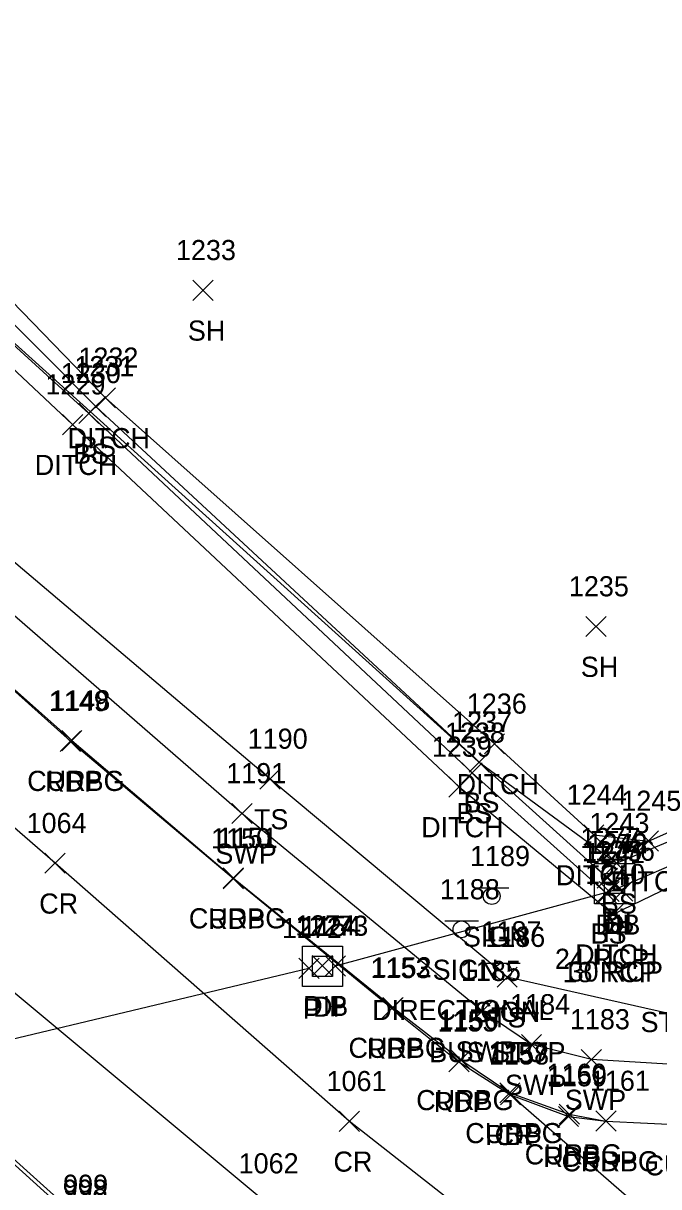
# Model space of a CAD drawing. Extents: x 1688195 to 1692013, y 424605 to 441234.
# Drawn here: x 1691891.2 to 1691954.3, y 439243.2 to 439358.8 of the extents above; entities that cross this region are included whole.
import ezdxf

# ---------------------------------------------------------------- set-up
doc = ezdxf.new("R2010")
doc.units = 0
for name, color, linetype in [('D_A', 7, 'Continuous'), ('D_C', 7, 'Continuous'), ('D_I', 7, 'Continuous'), ('D_TIC', 7, 'Continuous'), ('DCP', 7, 'Continuous'), ('DD', 7, 'Continuous'), ('DS', 7, 'Continuous'), ('L_A', 7, 'Continuous'), ('L_I', 7, 'Continuous'), ('L_TIC', 7, 'Continuous'), ('LELB', 7, 'Continuous'), ('P_A', 7, 'Continuous'), ('P_I', 7, 'Continuous'), ('P_TIC', 7, 'Continuous'), ('PET', 7, 'Continuous'), ('PRC', 7, 'Continuous'), ('R_A', 7, 'Continuous'), ('R_I', 7, 'Continuous'), ('R_TIC', 7, 'Continuous'), ('RC', 7, 'Continuous'), ('RSW', 7, 'Continuous'), ('S_A', 7, 'Continuous'), ('S_C', 7, 'Continuous'), ('S_I', 7, 'Continuous'), ('SSGN', 7, 'Continuous')]:
    doc.layers.add(name, color=color, linetype=linetype)

msp = doc.modelspace()

# ---------------------------------------------------------------- linework, layer by layer
at = {"layer": 'D_TIC'}
for points in [[(1691898.36, 439320.57), (1691900.36, 439322.57)], [(1691900.36, 439320.57), (1691898.36, 439322.57)], [(1691895.1, 439317.91), (1691897.1, 439319.91)], [(1691897.1, 439317.91), (1691895.1, 439319.91)], [(1691936.96, 439286.21), (1691938.96, 439288.21)], [(1691938.96, 439286.21), (1691936.96, 439288.21)], [(1691933.44, 439281.93), (1691935.44, 439283.93)], [(1691935.44, 439281.93), (1691933.44, 439283.93)], [(1691946.81, 439277.16), (1691948.81, 439279.16)], [(1691948.81, 439277.16), (1691946.81, 439279.16)], [(1691952.23, 439276.56), (1691954.23, 439278.56)], [(1691954.23, 439276.56), (1691952.23, 439278.56)], [(1691948.16, 439272.86), (1691950.16, 439274.86)], [(1691950.16, 439272.86), (1691948.16, 439274.86)], [(1691948.34, 439271.54), (1691950.34, 439273.54)], [(1691950.34, 439271.54), (1691948.34, 439273.54)], [(1691948.87, 439272.26), (1691950.87, 439274.26)], [(1691950.87, 439272.26), (1691948.87, 439274.26)], [(1691949.67, 439271.6), (1691951.67, 439273.6)], [(1691951.67, 439271.6), (1691949.67, 439273.6)], [(1691948.73, 439269.29), (1691950.73, 439271.29)], [(1691950.73, 439269.29), (1691948.73, 439271.29)], [(1691918.55, 439263.92), (1691920.55, 439265.92)], [(1691920.55, 439263.92), (1691918.55, 439265.92)], [(1691919.88, 439264.18), (1691921.88, 439266.18)], [(1691921.88, 439264.18), (1691919.88, 439266.18)], [(1691921.17, 439264.15), (1691923.17, 439266.15)], [(1691923.17, 439264.15), (1691921.17, 439266.15)]]:
    msp.add_lwpolyline(points, dxfattribs=at)
at = {"layer": 'DCP'}
for points in [[(1691949.16, 439273.86), (1691789.03, 439418.46)], [(1691922.17, 439265.15), (1691949.34, 439272.54)], [(1691871.63, 439253.48), (1691919.55, 439264.92)]]:
    msp.add_lwpolyline(points, dxfattribs=at)
at = {"layer": 'DD'}
for points in [[(1691845, 439386.65), (1691846.96, 439371.91), (1691853.76, 439362.04), (1691874.03, 439339.66), (1691896.1, 439318.91), (1691934.44, 439282.93), (1691949.73, 439270.29), (1691969.73, 439279.96), (1691978.58, 439270.8)], [(1691849.48, 439383.4), (1691851.48, 439372.69), (1691857.96, 439364.8), (1691877.63, 439343.99), (1691899.36, 439321.57), (1691937.96, 439287.21), (1691947.81, 439278.16), (1691953.23, 439277.56), (1691972.91, 439286.3), (1691980.77, 439274.16), (1691984.62, 439267.72)]]:
    msp.add_lwpolyline(points, dxfattribs=at)
at = {"layer": 'DS'}
for p, q in [((1691947.87, 439275.33), (1691951.87, 439275.33)), ((1691947.87, 439271.33), (1691947.87, 439275.33)), ((1691951.87, 439275.33), (1691951.87, 439271.33)), ((1691948.87, 439272.33), (1691948.87, 439274.33)), ((1691948.87, 439274.33), (1691950.87, 439274.33)), ((1691950.87, 439274.33), (1691950.87, 439272.33)), ((1691950.87, 439272.33), (1691948.87, 439272.33)), ((1691949.87, 439273.33), (1691949.87, 439273.33)), ((1691949.87, 439273.33), (1691949.87, 439273.33)), ((1691951.87, 439271.33), (1691947.87, 439271.33)), ((1691918.89, 439267.11), (1691922.89, 439267.11)), ((1691918.89, 439263.11), (1691918.89, 439267.11)), ((1691922.89, 439267.11), (1691922.89, 439263.11)), ((1691919.89, 439264.11), (1691919.89, 439266.11)), ((1691919.89, 439266.11), (1691921.89, 439266.11)), ((1691921.89, 439266.11), (1691921.89, 439264.11)), ((1691920.9, 439265.11), (1691920.9, 439265.11)), ((1691920.9, 439265.11), (1691920.9, 439265.11)), ((1691922.89, 439263.11), (1691918.89, 439263.11)), ((1691921.89, 439264.11), (1691919.89, 439264.11))]:
    msp.add_line(p, q, dxfattribs=at)
at = {"layer": 'L_TIC'}
for points in [[(1691908.04, 439331.25), (1691910.04, 439333.25)], [(1691910.04, 439331.25), (1691908.04, 439333.25)], [(1691896.71, 439319.03), (1691898.71, 439321.03)], [(1691898.71, 439319.03), (1691896.71, 439321.03)], [(1691897.4, 439319.72), (1691899.4, 439321.72)], [(1691899.4, 439319.72), (1691897.4, 439321.72)], [(1691947.03, 439297.86), (1691949.03, 439299.86)], [(1691949.03, 439297.86), (1691947.03, 439299.86)], [(1691935.44, 439284.39), (1691937.44, 439286.39)], [(1691937.44, 439284.39), (1691935.44, 439286.39)], [(1691934.73, 439283.32), (1691936.73, 439285.32)], [(1691936.73, 439283.32), (1691934.73, 439285.32)], [(1691914.68, 439282.72), (1691916.68, 439284.72)], [(1691916.68, 439282.72), (1691914.68, 439284.72)], [(1691949.07, 439274.35), (1691951.07, 439276.35)], [(1691951.07, 439274.35), (1691949.07, 439276.35)], [(1691948.05, 439271.37), (1691950.05, 439273.37)], [(1691950.05, 439271.37), (1691948.05, 439273.37)], [(1691938.22, 439263.04), (1691940.22, 439265.04)], [(1691940.22, 439263.04), (1691938.22, 439265.04)]]:
    msp.add_lwpolyline(points, dxfattribs=at)
at = {"layer": 'LELB'}
for points in [[(1691975.61, 439270.6), (1691971.42, 439266.02), (1691960.53, 439259.24), (1691939.22, 439264.04), (1691915.68, 439283.72), (1691886.97, 439308.05), (1691860.47, 439334.67), (1691845.99, 439348.3), (1691840.06, 439356.7), (1691834.35, 439370.12), (1691833.78, 439391.58)], [(1691846.65, 439384.74), (1691848.68, 439371.88), (1691855.16, 439363.03), (1691875.02, 439340.72), (1691897.71, 439320.03), (1691935.73, 439284.32), (1691949.05, 439272.37), (1691970.06, 439281.46), (1691980.12, 439271.73), (1691983.03, 439266.51)], [(1691847.58, 439384.47), (1691849.65, 439372.1), (1691856.36, 439363.87), (1691876.41, 439342.83), (1691898.4, 439320.72), (1691936.44, 439285.39), (1691950.07, 439275.35), (1691972.13, 439284.54), (1691980.12, 439271.73)]]:
    msp.add_lwpolyline(points, dxfattribs=at)
at = {"layer": 'P_TIC'}
for points in [[(1691894.87, 439286.46), (1691896.87, 439288.46)], [(1691896.87, 439286.46), (1691894.87, 439288.46)], [(1691893.35, 439274.35), (1691895.35, 439276.35)], [(1691895.35, 439274.35), (1691893.35, 439276.35)], [(1691911.05, 439272.82), (1691913.05, 439274.82)], [(1691913.05, 439272.82), (1691911.05, 439274.82)], [(1691926.79, 439259.94), (1691928.79, 439261.94)], [(1691928.79, 439259.94), (1691926.79, 439261.94)], [(1691933.43, 439254.64), (1691935.43, 439256.64)], [(1691935.43, 439254.64), (1691933.43, 439256.64)], [(1691938.54, 439251.36), (1691940.54, 439253.36)], [(1691940.54, 439251.36), (1691938.54, 439253.36)], [(1691938.54, 439251.36), (1691940.54, 439253.36)], [(1691940.54, 439251.36), (1691938.54, 439253.36)], [(1691922.55, 439248.72), (1691924.55, 439250.72)], [(1691924.55, 439248.72), (1691922.55, 439250.72)], [(1691944.3, 439249.2), (1691946.3, 439251.2)], [(1691946.3, 439249.2), (1691944.3, 439251.2)], [(1691948.02, 439248.75), (1691950.02, 439250.75)], [(1691950.02, 439248.75), (1691948.02, 439250.75)]]:
    msp.add_lwpolyline(points, dxfattribs=at)
at = {"layer": 'PET'}
for points in [[(1691800.95, 439315.05), (1691800.71, 439316.53), (1691801.54, 439317.59), (1691803.01, 439317.75), (1691817.06, 439309.7), (1691828.51, 439300.65), (1691844.68, 439285.42), (1691865.17, 439267.39), (1691884.85, 439250.83), (1691897.53, 439239.42), (1691910.3, 439227.43), (1691911.52, 439225.27), (1691910.89, 439223.79), (1691909.81, 439223.42), (1691908.76, 439223.6), (1691890.09, 439233.4), (1691870.38, 439245.17), (1691862.38, 439250.39), (1691860.03, 439251.8), (1691851, 439258.94), (1691829.1, 439279.04), (1691821.39, 439286.91), (1691810.78, 439300.43)], [(1691876.93, 439304.47), (1691895.87, 439287.46), (1691912.05, 439273.82), (1691927.79, 439260.94), (1691934.43, 439255.64), (1691939.54, 439252.36), (1691945.3, 439250.2), (1691949.02, 439249.75), (1691957.26, 439249.35), (1691965.7, 439251.38), (1691970.56, 439254.07), (1691975.68, 439258.27), (1691977.47, 439260.47), (1691979.88, 439263.5), (1691983.03, 439266.51), (1691984.62, 439267.72)]]:
    msp.add_lwpolyline(points, dxfattribs=at)
at = {"layer": 'PRC'}
for points in [[(1691980.66, 439193.96), (1691949.03, 439215.61), (1691915.39, 439241.55), (1691887.2, 439265.05), (1691850.38, 439298.07), (1691824.99, 439321.73), (1691796.94, 439350.89), (1691771.5, 439379.22), (1691742.05, 439414.41)], [(1691957.02, 439223.44), (1691923.55, 439249.72), (1691894.35, 439275.35), (1691862.96, 439302.59), (1691832.42, 439330.49), (1691805.17, 439357.5)], [(1691939.54, 439252.36), (1691968.23, 439227.36), (1692010.35, 439194.63)]]:
    msp.add_lwpolyline(points, dxfattribs=at)
at = {"layer": 'R_TIC'}
for points in [[(1691895.01, 439286.53), (1691897.01, 439288.53)], [(1691897.01, 439286.53), (1691895.01, 439288.53)], [(1691911.9, 439279.3), (1691913.9, 439281.3)], [(1691913.9, 439279.3), (1691911.9, 439281.3)], [(1691911.05, 439272.88), (1691913.05, 439274.88)], [(1691913.05, 439272.88), (1691911.05, 439274.88)], [(1691926.89, 439260.02), (1691928.89, 439262.02)], [(1691928.89, 439260.02), (1691926.89, 439262.02)], [(1691935.74, 439259.66), (1691937.74, 439261.66)], [(1691937.74, 439259.66), (1691935.74, 439261.66)], [(1691940.63, 439256.35), (1691942.63, 439258.35)], [(1691942.63, 439256.35), (1691940.63, 439258.35)], [(1691933.61, 439254.83), (1691935.61, 439256.83)], [(1691935.61, 439254.83), (1691933.61, 439256.83)], [(1691946.57, 439254.86), (1691948.57, 439256.86)], [(1691948.57, 439254.86), (1691946.57, 439256.86)], [(1691938.48, 439251.55), (1691940.48, 439253.55)], [(1691940.48, 439251.55), (1691938.48, 439253.55)], [(1691944.38, 439249.44), (1691946.38, 439251.44)], [(1691946.38, 439249.44), (1691944.38, 439251.44)], [(1691948.02, 439248.75), (1691950.02, 439250.75)], [(1691950.02, 439248.75), (1691948.02, 439250.75)]]:
    msp.add_lwpolyline(points, dxfattribs=at)
at = {"layer": 'RC'}
for points in [[(1691827.7, 439394.92), (1691826.17, 439390.37), (1691824.81, 439382.88), (1691824.34, 439378.12), (1691824.34, 439373.75), (1691825.06, 439368.5), (1691826.85, 439361.6), (1691828.4, 439357.54), (1691830.44, 439353.69), (1691834.78, 439346.96), (1691839.16, 439341.39), (1691852.5, 439327.72), (1691876.91, 439304.53), (1691896.01, 439287.53), (1691912.05, 439273.88), (1691927.89, 439261.02), (1691934.61, 439255.83), (1691939.48, 439252.55), (1691945.38, 439250.44), (1691949.02, 439249.75)], [(1691801.25, 439315.04), (1691801.11, 439316.33), (1691801.76, 439317.38), (1691802.82, 439317.35), (1691816.87, 439309.41), (1691828.25, 439300.3), (1691844.42, 439285.11), (1691865.02, 439267.12), (1691884.74, 439250.47), (1691897.46, 439238.93), (1691910.16, 439227.13), (1691911.27, 439225.37), (1691910.65, 439224.03), (1691909.84, 439223.78), (1691908.93, 439223.98), (1691890.41, 439233.73), (1691870.59, 439245.45), (1691863.21, 439250.36), (1691862.38, 439250.39)]]:
    msp.add_lwpolyline(points, dxfattribs=at)
at = {"layer": 'RSW'}
msp.add_lwpolyline([(1691977.46, 439268.16), (1691972.67, 439263.18), (1691966.62, 439257.98), (1691961.86, 439255.83), (1691956.78, 439255.3), (1691947.57, 439255.86), (1691941.63, 439257.35), (1691936.74, 439260.66), (1691912.9, 439280.3), (1691884.49, 439305), (1691857.04, 439330.93), (1691842.61, 439345.6), (1691837.43, 439352.31), (1691833.75, 439359.53), (1691830.58, 439369.1), (1691830.34, 439383.86), (1691832.59, 439392.6)], dxfattribs=at)
at = {"layer": 'SSGN'}
for p, q in [((1691936.04, 439272.92), (1691939.37, 439272.92)), ((1691937.68, 439272.09), (1691937.68, 439272.09)), ((1691933.03, 439269.62), (1691936.36, 439269.62)), ((1691934.68, 439268.79), (1691934.68, 439268.79)), ((1691937.17, 439265.44), (1691940.5, 439265.44)), ((1691938.82, 439264.61), (1691938.82, 439264.61))]:
    msp.add_line(p, q, dxfattribs=at)
for centre in [(1691937.68, 439272.09), (1691934.68, 439268.79), (1691938.82, 439264.61)]:
    msp.add_circle(centre, 0.833, dxfattribs=at)

# ---------------------------------------------------------------- texts
at = {"layer": 'D_A'}
for s, p in [('DITCH', (1691895.6, 439316.57)), ('DITCH', (1691892.34, 439313.91)), ('DITCH', (1691934.2, 439282.21)), ('DITCH', (1691930.68, 439277.93)), ('DITCH', (1691944.05, 439273.16)), ('DITCH', (1691949.47, 439272.56)), ('DIB', (1691947.97, 439268.26)), ('P', (1691948.54, 439268.86)), ('DI', (1691948.93, 439268.33)), ('P', (1691948.72, 439267.54)), ('P', (1691950.05, 439267.6)), ('DITCH', (1691945.96, 439265.29)), ('P', (1691918.93, 439259.92)), ('DIB', (1691918.98, 439260.18)), ('DI', (1691919.95, 439260.11)), ('P', (1691921.55, 439260.15))]:
    msp.add_text(s, height=2, dxfattribs=at).set_placement(p)
at = {"layer": 'D_C'}
for s, p in [('24 RCP', (1691943.95, 439264.86)), ('18 RCP', (1691944.7, 439263.54)), ('30 RCP', (1691945.31, 439263.6))]:
    msp.add_text(s, height=2, dxfattribs=at).set_placement(p)
at = {"layer": 'D_I'}
for s, p in [('1232', (1691896.67, 439324.57)), ('1229', (1691893.4, 439321.91)), ('1236', (1691935.21, 439290.21)), ('1239', (1691931.74, 439285.93)), ('1244', (1691945.12, 439281.16)), ('1245', (1691950.54, 439280.56)), ('1277', (1691946.47, 439276.86)), ('1242', (1691947.18, 439276.33)), ('1278', (1691947.18, 439276.26)), ('1275', (1691946.65, 439275.54)), ('1276', (1691947.92, 439275.6)), ('1240', (1691946.95, 439273.29)), ('1272', (1691916.86, 439267.92)), ('1274', (1691918.19, 439268.18)), ('1154', (1691918.77, 439268.11)), ('1273', (1691919.48, 439268.15))]:
    msp.add_text(s, height=2, dxfattribs=at).set_placement(p)
at = {"layer": 'L_A'}
for s, p in [('SH', (1691907.53, 439327.25)), ('BS', (1691896.84, 439315.72)), ('BS', (1691896.15, 439315.03)), ('SH', (1691946.52, 439293.86)), ('BS', (1691934.88, 439280.39)), ('TS', (1691914.09, 439278.72)), ('BS', (1691934.17, 439279.32)), ('BS', (1691948.51, 439270.35)), ('BS', (1691947.49, 439267.37)), ('TS', (1691937.63, 439259.04))]:
    msp.add_text(s, height=2, dxfattribs=at).set_placement(p)
at = {"layer": 'L_I'}
for s, p in [('1233', (1691906.35, 439335.25)), ('1231', (1691896.27, 439323.72)), ('1230', (1691894.93, 439323.03)), ('1235', (1691945.34, 439301.86)), ('1237', (1691933.74, 439288.39)), ('1190', (1691913.47, 439286.72)), ('1238', (1691933.04, 439287.32)), ('1243', (1691947.38, 439278.35)), ('1241', (1691946.93, 439275.37)), ('1186', (1691937.04, 439267.04))]:
    msp.add_text(s, height=2, dxfattribs=at).set_placement(p)
at = {"layer": 'P_A'}
for s, p in [('RDP', (1691893.36, 439282.46)), ('CR', (1691892.78, 439270.35)), ('RDP', (1691909.54, 439268.82)), ('RDP', (1691925.27, 439255.94)), ('RDP', (1691931.92, 439250.64)), ('RDP', (1691937.03, 439247.36)), ('CR', (1691937.97, 439247.36)), ('RDP', (1691942.79, 439245.2)), ('CR', (1691921.98, 439244.72)), ('RDP', (1691946.51, 439244.75))]:
    msp.add_text(s, height=2, dxfattribs=at).set_placement(p)
at = {"layer": 'P_I'}
for s, p in [('1149', (1691893.74, 439290.46)), ('1064', (1691891.53, 439278.35)), ('1150', (1691909.83, 439276.82)), ('1153', (1691925.66, 439263.94)), ('1155', (1691932.3, 439258.64)), ('1158', (1691937.42, 439255.36)), ('1158', (1691937.42, 439255.36)), ('1159', (1691943.17, 439253.2)), ('1061', (1691921.29, 439252.72)), ('1161', (1691947.42, 439252.75)), ('1062', (1691912.57, 439244.55)), ('999', (1691895.16, 439242.42))]:
    msp.add_text(s, height=2, dxfattribs=at).set_placement(p)
at = {"layer": 'R_A'}
for s, p in [('CURBG', (1691891.59, 439282.53)), ('SWP', (1691910.26, 439275.3)), ('CURBG', (1691907.63, 439268.88)), ('CURBG', (1691923.47, 439256.02)), ('SWP', (1691934.1, 439255.66)), ('SWP', (1691939, 439252.35)), ('CURBG', (1691930.19, 439250.83)), ('SWP', (1691944.93, 439250.86)), ('CURBG', (1691935.06, 439247.55)), ('CURBG', (1691940.96, 439245.44)), ('CURBG', (1691944.61, 439244.75)), ('CURBG', (1691952.85, 439244.35))]:
    msp.add_text(s, height=2, dxfattribs=at).set_placement(p)
at = {"layer": 'R_I'}
for s, p in [('1148', (1691893.88, 439290.53)), ('1191', (1691911.34, 439283.3)), ('1151', (1691910.49, 439276.88)), ('1152', (1691925.76, 439264.02)), ('1185', (1691934.62, 439263.66)), ('1184', (1691939.51, 439260.35)), ('1156', (1691932.43, 439258.83)), ('1183', (1691945.44, 439258.86)), ('1157', (1691937.36, 439255.55)), ('1160', (1691943.12, 439253.44)), ('1161', (1691947.42, 439252.75)), ('998', (1691895.1, 439241.93))]:
    msp.add_text(s, height=2, dxfattribs=at).set_placement(p)
at = {"layer": 'S_A'}
for p in [(1691934.82, 439267.07), (1691931.82, 439263.77), (1691935.95, 439259.59)]:
    msp.add_text('SIGN', height=2, dxfattribs=at).set_placement(p)
at = {"layer": 'S_C'}
for s, p in [('DIRECTIONAL', (1691925.82, 439259.77)), ('STREET SIGN AND DEAD END', (1691952.45, 439258.58)), ('BUS STOP', (1691931.48, 439255.59))]:
    msp.add_text(s, height=2, dxfattribs=at).set_placement(p)
at = {"layer": 'S_I'}
for s, p in [('1189', (1691935.53, 439275.07)), ('1188', (1691932.53, 439271.77)), ('1187', (1691936.67, 439267.59))]:
    msp.add_text(s, height=2, dxfattribs=at).set_placement(p)

doc.saveas('drawing.dxf')
